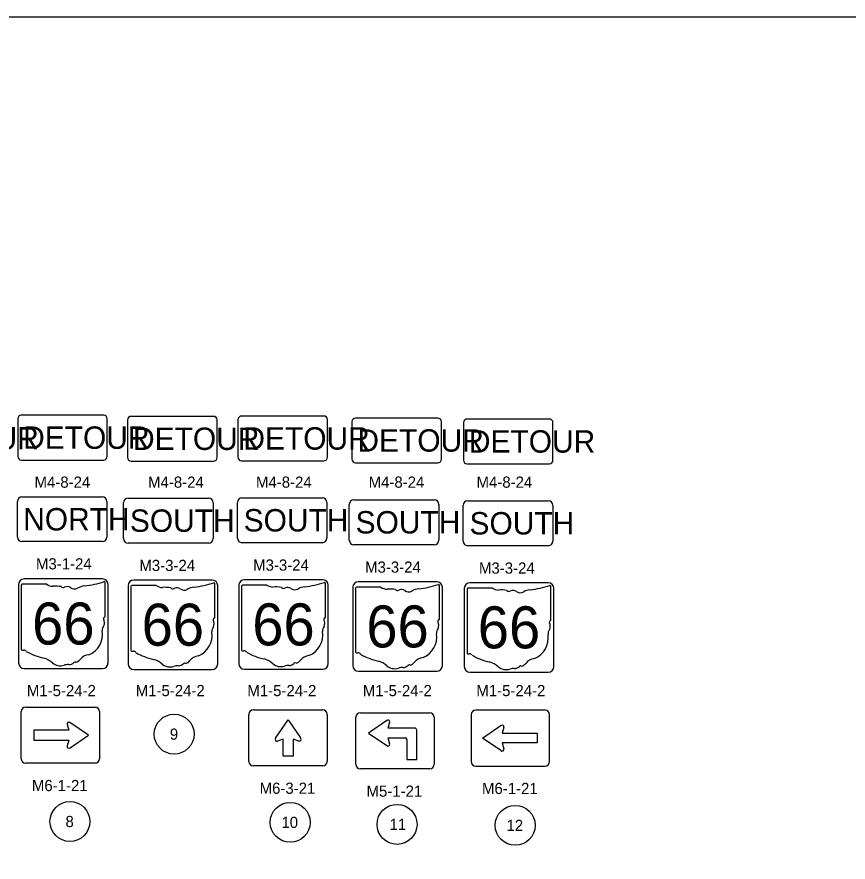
# Model space of a CAD drawing. Extents: x -87 to 2145, y -2128 to 440.
# Drawn here: x 565.1 to 750.8, y -339.7 to -150.9 of the extents above; entities that cross this region are included whole.
import ezdxf

# ---------------------------------------------------------------- set-up
doc = ezdxf.new("R2010")
doc.units = 0
for name, color, linetype in [('Default', 7, 'Continuous'), ('SC_Scratch1', 7, 'Continuous'), ('SN_P_Signs', 7, 'Continuous'), ('SN_P_Text', 7, 'Continuous')]:
    doc.layers.add(name, color=color, linetype=linetype)

msp = doc.modelspace()

# ---------------------------------------------------------------- linework, layer by layer
at = {"layer": 'Default'}
for centre in [(600.26, -311.12), (576.98, -330.63), (626.19, -330.82), (650.06, -331.27), (676.46, -331.49)]:
    msp.add_circle(centre, 4.46, dxfattribs=at)
at = {"layer": 'SC_Scratch1'}
msp.add_lwpolyline([(-86.99, -150.94), (902.07, -150.94), (902.07, -726.16), (-86.99, -726.16)], close=True, dxfattribs=at)
at = {"layer": 'SN_P_Signs'}
for p, q in [((566.24, -258.13), (584.24, -258.13)), ((589.98, -258.44), (607.98, -258.44)), ((615.39, -258.36), (633.39, -258.36)), ((565.24, -267.13), (565.24, -259.13)), ((585.24, -259.13), (585.24, -267.13)), ((588.98, -267.44), (588.98, -259.44)), ((608.98, -259.44), (608.98, -267.44)), ((614.39, -267.36), (614.39, -259.36)), ((634.39, -259.36), (634.39, -267.36)), ((639.4, -267.81), (639.4, -259.81)), ((640.4, -258.81), (658.4, -258.81)), ((659.4, -259.81), (659.4, -267.81)), ((664.85, -268.03), (664.85, -260.03)), ((665.85, -259.03), (683.85, -259.03)), ((684.85, -260.03), (684.85, -268.03)), ((584.24, -268.13), (566.24, -268.13)), ((607.98, -268.44), (589.98, -268.44)), ((633.39, -268.36), (615.39, -268.36)), ((658.4, -268.81), (640.4, -268.81)), ((683.85, -269.03), (665.85, -269.03)), ((584.87, -284.73), (584.87, -277.29)), ((634.07, -284.92), (634.07, -277.47)), ((566.12, -277.89), (566.12, -292.12)), ((571.8, -277.64), (566.31, -277.64)), ((590.6, -278.15), (590.6, -292.38)), ((596.28, -277.9), (590.79, -277.9)), ((609.35, -284.99), (609.35, -277.55)), ((615.32, -278.07), (615.32, -292.3)), ((620.99, -277.82), (615.5, -277.82)), ((640.79, -278.52), (640.79, -292.75)), ((646.47, -278.28), (640.98, -278.28)), ((659.54, -285.37), (659.54, -277.93)), ((665.69, -278.74), (665.69, -292.97)), ((671.37, -278.49), (665.88, -278.49)), ((684.44, -285.58), (684.44, -278.14)), ((584.87, -284.73), (584.87, -284.73)), ((609.35, -284.99), (609.35, -284.99)), ((634.07, -284.91), (634.07, -284.92)), ((659.54, -285.37), (659.54, -285.37)), ((684.44, -285.58), (684.44, -285.58)), ((567.11, -305.1), (582.61, -305.1)), ((617.97, -305.7), (633.47, -305.7)), ((683.15, -305.75), (667.65, -305.75)), ((683.15, -305.75), (683.15, -305.75)), ((566.11, -316.6), (566.11, -306.1)), ((583.61, -306.1), (583.61, -316.6)), ((616.97, -317.2), (616.97, -306.7)), ((634.47, -306.7), (634.47, -317.2)), ((640.86, -317.85), (640.86, -307.35)), ((641.86, -306.35), (657.36, -306.35)), ((658.36, -307.35), (658.36, -317.85)), ((666.65, -306.75), (666.65, -317.25)), ((684.15, -317.25), (684.15, -306.75)), ((576.34, -308.98), (576.73, -310.26)), ((581.11, -311.35), (576.97, -308.51)), ((622.88, -312.02), (625.72, -307.89)), ((625.72, -307.89), (628.52, -311.97)), ((647.75, -308.08), (643.67, -310.88)), ((648.05, -309.78), (648.46, -308.38)), ((669.15, -312), (673.29, -309.15)), ((576.73, -310.26), (568.92, -310.26)), ((568.92, -310.26), (568.92, -312.45)), ((577.03, -314.15), (581.11, -311.35)), ((643.67, -310.88), (647.75, -313.67)), ((653.98, -309.78), (648.05, -309.78)), ((653.98, -309.78), (653.98, -309.78)), ((654.45, -316.82), (654.45, -310.25)), ((673.93, -309.62), (673.53, -310.9)), ((673.53, -310.9), (681.34, -310.9)), ((681.34, -310.9), (681.34, -313.09)), ((568.92, -312.45), (576.73, -312.45)), ((576.73, -312.45), (576.34, -313.73)), ((624.63, -312.26), (623.35, -312.66)), ((624.63, -316.01), (624.63, -312.26)), ((628.1, -312.66), (626.82, -312.26)), ((626.82, -312.26), (626.82, -316.01)), ((648.46, -313.38), (648.05, -311.97)), ((648.05, -311.97), (651.95, -311.97)), ((652.26, -312.28), (652.26, -316.82)), ((673.23, -314.79), (669.15, -312)), ((681.34, -313.09), (673.53, -313.09)), ((673.53, -313.09), (673.93, -314.37)), ((626.82, -316.01), (624.63, -316.01)), ((652.26, -316.82), (654.45, -316.82)), ((652.26, -316.82), (654.45, -316.82)), ((582.61, -317.6), (567.11, -317.6)), ((633.47, -318.2), (617.97, -318.2)), ((657.36, -318.85), (641.86, -318.85)), ((667.65, -318.25), (683.15, -318.25))]:
    msp.add_line(p, q, dxfattribs=at)
for points in [[(565.32, -240.7), (565.32, -249.1)], [(584.52, -239.9), (566.12, -239.9)], [(585.32, -249.1), (585.32, -240.7)], [(589.86, -240.95), (589.86, -249.35)], [(609.06, -240.15), (590.66, -240.15)], [(609.86, -249.35), (609.86, -240.95)], [(614.52, -240.88), (614.52, -249.28)], [(633.72, -240.08), (615.32, -240.08)], [(634.52, -249.28), (634.52, -240.88)], [(639.99, -241.33), (639.99, -249.73)], [(659.19, -240.53), (640.79, -240.53)], [(659.99, -249.73), (659.99, -241.33)], [(664.89, -241.55), (664.89, -249.95)], [(684.09, -240.75), (665.69, -240.75)], [(684.89, -249.95), (684.89, -241.55)], [(566.12, -249.9), (584.52, -249.9)], [(590.66, -250.15), (609.06, -250.15)], [(615.32, -250.08), (633.72, -250.08)], [(640.79, -250.53), (659.19, -250.53)], [(665.69, -250.75), (684.09, -250.75)], [(584.26, -276.45), (566.76, -276.45)], [(608.74, -276.7), (591.24, -276.7)], [(633.46, -276.63), (615.96, -276.63)], [(658.93, -277.08), (641.43, -277.08)], [(683.83, -277.3), (666.33, -277.3)], [(565.51, -277.7), (565.51, -295.2)], [(585.51, -295.2), (585.51, -277.7)], [(589.99, -277.95), (589.99, -295.45)], [(609.99, -295.45), (609.99, -277.95)], [(614.71, -277.88), (614.71, -295.38)], [(634.71, -295.38), (634.71, -277.88)], [(640.18, -278.33), (640.18, -295.83)], [(660.18, -295.83), (660.18, -278.33)], [(665.08, -278.55), (665.08, -296.05)], [(685.08, -296.05), (685.08, -278.55)], [(566.76, -296.45), (584.26, -296.45)], [(591.24, -296.7), (608.74, -296.7)], [(615.96, -296.63), (633.46, -296.63)], [(641.43, -297.08), (658.93, -297.08)], [(666.33, -297.3), (683.83, -297.3)]]:
    msp.add_lwpolyline(points, dxfattribs=at)
for centre, radius, start, end in [((566.12, -240.7), 0.8, 90, 180), ((584.52, -240.7), 0.8, 0, 90), ((590.66, -240.95), 0.8, 90, 180), ((609.06, -240.95), 0.8, 0, 90), ((615.32, -240.88), 0.8, 90, 180), ((633.72, -240.88), 0.8, 0, 90), ((640.79, -241.33), 0.8, 90, 180), ((659.19, -241.33), 0.8, 0, 90), ((665.69, -241.55), 0.8, 90, 180), ((684.09, -241.55), 0.8, 0, 90), ((566.12, -249.1), 0.8, 180, 270), ((584.52, -249.1), 0.8, 270, 0), ((590.66, -249.35), 0.8, 180, 270), ((609.06, -249.35), 0.8, 270, 0), ((615.32, -249.28), 0.8, 180, 270), ((633.72, -249.28), 0.8, 270, 0), ((640.79, -249.73), 0.8, 180, 270), ((659.19, -249.73), 0.8, 270, 0), ((665.69, -249.95), 0.8, 180, 270), ((684.09, -249.95), 0.8, 270, 0), ((566.24, -259.13), 1, 90, 180), ((584.24, -259.13), 1, 0, 90), ((589.98, -259.44), 1, 90, 180), ((607.98, -259.44), 1, 0, 90), ((615.39, -259.36), 1, 90, 180), ((633.39, -259.36), 1, 0, 90), ((640.4, -259.81), 1, 90, 180), ((658.4, -259.81), 1, 0, 90), ((665.85, -260.03), 1, 90, 180), ((683.85, -260.03), 1, 0, 90), ((566.24, -267.13), 1, 180, 270), ((584.24, -267.13), 1, 270, 0), ((589.98, -267.44), 1, 180, 270), ((607.98, -267.44), 1, 270, 0), ((615.39, -267.36), 1, 180, 270), ((633.39, -267.36), 1, 270, 0), ((640.4, -267.81), 1, 180, 270), ((658.4, -267.81), 1, 270, 0), ((665.85, -268.03), 1, 180, 270), ((683.85, -268.03), 1, 270, 0), ((566.76, -277.7), 1.25, 90, 180), ((578.19, -258.24), 19.88, 275.8445, 288.9065), ((584.26, -277.7), 1.25, 0, 90), ((584.66, -277.26), 0.209, 351.8621, 97.738), ((591.24, -277.95), 1.25, 90, 180), ((602.67, -258.5), 19.88, 275.8445, 288.9065), ((608.74, -277.95), 1.25, 0, 90), ((609.15, -277.52), 0.209, 351.8621, 97.738), ((615.96, -277.88), 1.25, 90, 180), ((627.39, -258.42), 19.88, 275.8445, 288.9065), ((633.46, -277.88), 1.25, 0, 90), ((633.86, -277.44), 0.209, 351.8621, 97.738), ((641.43, -278.33), 1.25, 90, 180), ((658.93, -278.33), 1.25, 0, 90), ((666.33, -278.55), 1.25, 90, 180), ((683.83, -278.55), 1.25, 0, 90), ((566.34, -277.86), 0.217, 98.1301, 188.1301), ((573.1, -275.99), 2.11, 231.6195, 271.1119), ((573.8, -285.63), 7.56, 80.4867, 94.9883), ((575.52, -277.78), 0.608, 219.7921, 297.1024), ((576.41, -279.43), 1.26, 54.4667, 119.1411), ((578.04, -277.17), 1.52, 233.8562, 294.8282), ((580.73, -281.99), 4, 97.3462, 120.7689), ((590.82, -278.12), 0.217, 98.1301, 188.1301), ((597.59, -276.25), 2.11, 231.6195, 271.1119), ((598.29, -285.89), 7.56, 80.4867, 94.9883), ((600, -278.04), 0.608, 219.7921, 297.1024), ((600.9, -279.69), 1.26, 54.4667, 119.1411), ((602.53, -277.43), 1.52, 233.8562, 294.8282), ((605.21, -282.25), 4, 97.3462, 120.7689), ((615.53, -278.04), 0.217, 98.1301, 188.1301), ((622.3, -276.17), 2.11, 231.6195, 271.1119), ((623, -285.81), 7.56, 80.4867, 94.9883), ((624.72, -277.96), 0.608, 219.7921, 297.1024), ((625.61, -279.61), 1.26, 54.4667, 119.1411), ((627.24, -277.35), 1.52, 233.8562, 294.8282), ((629.93, -282.17), 4, 97.3462, 120.7689), ((641.01, -278.49), 0.217, 98.1301, 188.1301), ((647.78, -276.63), 2.11, 231.6195, 271.1119), ((648.48, -286.27), 7.56, 80.4867, 94.9883), ((650.19, -278.42), 0.608, 219.7921, 297.1024), ((651.09, -280.06), 1.26, 54.4667, 119.1411), ((652.72, -277.81), 1.52, 233.8562, 294.8282), ((655.4, -282.62), 4, 97.3462, 120.7689), ((652.86, -258.88), 19.88, 275.8445, 288.9065), ((659.34, -277.89), 0.209, 351.8621, 97.738), ((665.91, -278.71), 0.217, 98.1301, 188.1301), ((672.68, -276.84), 2.11, 231.6195, 271.1119), ((673.37, -286.48), 7.56, 80.4867, 94.9883), ((675.09, -278.63), 0.608, 219.7921, 297.1024), ((675.98, -280.28), 1.26, 54.4667, 119.1411), ((677.61, -278.02), 1.52, 233.8562, 294.8282), ((680.3, -282.84), 4, 97.3462, 120.7689), ((677.76, -259.09), 19.88, 275.8445, 288.9065), ((684.23, -278.11), 0.209, 351.8621, 97.738), ((584.82, -285.28), 0.323, 107.944, 210.337), ((584.65, -284.76), 0.223, 289.6038, 7.7341), ((609.13, -285.02), 0.223, 289.6038, 7.7341), ((633.85, -284.94), 0.223, 289.6038, 7.7341), ((585.62, -287.85), 1.41, 136.8065, 186.9296), ((582.77, -286.22), 1.94, 340.033, 23.6496), ((609.31, -285.54), 0.323, 107.944, 210.337), ((607.25, -286.48), 1.94, 340.033, 23.6496), ((634.02, -285.46), 0.323, 107.944, 210.337), ((631.97, -286.4), 1.94, 340.033, 23.6496), ((659.5, -285.92), 0.323, 107.944, 210.337), ((657.44, -286.86), 1.94, 340.033, 23.6496), ((659.32, -285.4), 0.223, 289.6038, 7.7341), ((684.39, -286.13), 0.323, 107.944, 210.337), ((682.34, -287.07), 1.94, 340.033, 23.6496), ((684.22, -285.61), 0.223, 289.6038, 7.7341), ((579.31, -288.8), 4.97, 292.3089, 8.9858), ((603.79, -289.06), 4.97, 292.3089, 8.9858), ((610.1, -288.11), 1.41, 136.8065, 186.9296), ((628.5, -288.98), 4.97, 292.3089, 8.9858), ((634.82, -288.03), 1.41, 136.8065, 186.9296), ((653.98, -289.43), 4.97, 292.3089, 8.9858), ((660.29, -288.48), 1.41, 136.8065, 186.9296), ((685.19, -288.7), 1.41, 136.8065, 186.9296), ((678.88, -289.65), 4.97, 292.3089, 8.9858), ((566.34, -292.15), 0.219, 171.9584, 258.3066), ((566.37, -290.69), 1.67, 267.339, 280.6039), ((566.71, -292.94), 0.603, 29.7484, 93.2717), ((590.82, -292.41), 0.219, 171.9584, 258.3066), ((615.54, -292.33), 0.219, 171.9584, 258.3066), ((615.57, -290.87), 1.67, 267.339, 280.6039), ((615.91, -293.12), 0.603, 29.7484, 93.2717), ((574.33, -280.15), 14.36, 240.4129, 257.1985), ((570.05, -298.51), 4.49, 47.1842, 75.836), ((577.95, -293.5), 1.61, 282.8732, 323.2771), ((581.4, -296.11), 2.72, 94.4031, 142.5768), ((590.85, -290.95), 1.67, 267.339, 280.6039), ((591.2, -293.2), 0.603, 29.7484, 93.2717), ((598.81, -280.41), 14.36, 240.4129, 257.1985), ((594.53, -298.77), 4.49, 47.1842, 75.836), ((605.89, -296.37), 2.72, 94.4031, 142.5768), ((623.52, -280.33), 14.36, 240.4129, 257.1985), ((619.24, -298.69), 4.49, 47.1842, 75.836), ((630.6, -296.29), 2.72, 94.4031, 142.5768), ((641.01, -292.78), 0.219, 171.9584, 258.3066), ((641.04, -291.33), 1.67, 267.339, 280.6039), ((641.39, -293.57), 0.603, 29.7484, 93.2717), ((649, -280.79), 14.36, 240.4129, 257.1985), ((656.08, -296.75), 2.72, 94.4031, 142.5768), ((665.91, -293), 0.219, 171.9584, 258.3066), ((665.94, -291.54), 1.67, 267.339, 280.6039), ((666.28, -293.79), 0.603, 29.7484, 93.2717), ((673.9, -281), 14.36, 240.4129, 257.1985), ((680.97, -296.96), 2.72, 94.4031, 142.5768), ((566.76, -295.2), 1.25, 180, 270), ((574.9, -293.01), 2.85, 230.7004, 286.2918), ((576.55, -297.93), 2.34, 85.6951, 111.2099), ((576.76, -294.08), 1.52, 268.777, 315.5493), ((578.13, -295.45), 0.428, 65.7517, 132.6484), ((584.26, -295.2), 1.25, 270, 0), ((591.24, -295.45), 1.25, 180, 270), ((599.39, -293.27), 2.85, 230.7004, 286.2918), ((601.03, -298.19), 2.34, 85.6951, 111.2099), ((601.24, -294.33), 1.52, 268.777, 315.5493), ((602.62, -295.71), 0.428, 65.7517, 132.6484), ((602.43, -293.76), 1.61, 282.8732, 323.2771), ((608.74, -295.45), 1.25, 270, 0), ((615.96, -295.38), 1.25, 180, 270), ((624.1, -293.19), 2.85, 230.7004, 286.2918), ((625.75, -298.11), 2.34, 85.6951, 111.2099), ((625.96, -294.26), 1.52, 268.777, 315.5493), ((627.33, -295.64), 0.428, 65.7517, 132.6484), ((627.15, -293.68), 1.61, 282.8732, 323.2771), ((633.46, -295.38), 1.25, 270, 0), ((641.43, -295.83), 1.25, 180, 270), ((644.72, -299.15), 4.49, 47.1842, 75.836), ((649.58, -293.65), 2.85, 230.7004, 286.2918), ((651.22, -298.57), 2.34, 85.6951, 111.2099), ((651.43, -294.71), 1.52, 268.777, 315.5493), ((652.81, -296.09), 0.428, 65.7517, 132.6484), ((652.62, -294.13), 1.61, 282.8732, 323.2771), ((658.93, -295.83), 1.25, 270, 0), ((666.33, -296.05), 1.25, 180, 270), ((669.62, -299.36), 4.49, 47.1842, 75.836), ((674.48, -293.86), 2.85, 230.7004, 286.2918), ((676.33, -294.93), 1.52, 268.777, 315.5493), ((677.7, -296.3), 0.428, 65.7517, 132.6484), ((677.52, -294.35), 1.61, 282.8732, 323.2771), ((683.83, -296.05), 1.25, 270, 0), ((676.12, -298.78), 2.34, 85.6951, 111.2099), ((567.11, -306.1), 1, 90, 180), ((582.61, -306.1), 1, 0, 90), ((617.97, -306.7), 1, 90, 180), ((633.47, -306.7), 1, 0, 90), ((667.65, -306.75), 1, 90, 180), ((683.15, -306.75), 1, 0, 90), ((641.86, -307.35), 1, 90, 180), ((657.36, -307.35), 1, 0, 90), ((576.73, -308.85), 0.417, 55.4112, 197.2046), ((648.05, -308.38), 0.417, 0.0017, 134.9999), ((673.53, -309.5), 0.417, 342.7954, 124.5888), ((653.98, -310.25), 0.469, 0, 90), ((623.22, -312.26), 0.417, 145.4112, 287.2046), ((628.22, -312.26), 0.417, 252.7954, 45.0096), ((651.95, -312.28), 0.312, 0, 90), ((576.73, -313.85), 0.417, 162.7954, 315.0096), ((648.05, -313.38), 0.417, 225.0001, 0.0017), ((673.53, -314.5), 0.417, 224.9904, 17.2046), ((567.11, -316.6), 1, 180, 270), ((582.61, -316.6), 1, 270, 360), ((617.97, -317.2), 1, 180, 270), ((633.47, -317.2), 1, 270, 0), ((641.86, -317.85), 1, 180, 270), ((657.36, -317.85), 1, 270, 360), ((667.65, -317.25), 1, 180, 270), ((683.15, -317.25), 1, 270, 0)]:
    msp.add_arc(centre, radius, start, end, dxfattribs=at)

# ---------------------------------------------------------------- texts
at = {"layer": 'Default'}
for s, p in [('9', (599.3, -312.37)), ('8', (575.99, -331.88)), ('10', (624.23, -332.07)), ('11', (648.38, -332.52)), ('12', (674.51, -332.74))]:
    msp.add_text(s, height=2.5, dxfattribs=at).set_placement(p)
at = {"layer": 'SN_P_Signs'}
for s, height, p in [('DETOUR', 5, (541.8, -247.55)), ('DETOUR', 5, (566.53, -247.4)), ('DETOUR', 5, (591.08, -247.65)), ('DETOUR', 5, (615.73, -247.58)), ('DETOUR', 5, (641.21, -248.03)), ('DETOUR', 5, (666.11, -248.25)), ('NORTH', 5, (566.54, -265.63)), ('SOUTH', 5, (590.38, -265.94)), ('SOUTH', 5, (615.79, -265.86)), ('SOUTH', 5, (640.8, -266.31)), ('SOUTH', 5, (666.25, -266.53)), ('66', 9.375, (568.53, -291.11)), ('66', 9.375, (593.01, -291.37)), ('66', 9.375, (617.72, -291.3)), ('66', 9.375, (643.2, -291.75)), ('66', 9.375, (668.1, -291.96))]:
    msp.add_text(s, height=height, dxfattribs=at).set_placement(p)
at = {"layer": 'SN_P_Text'}
for s, p in [('M4-8-24', (569.08, -256.09)), ('M4-8-24', (594.44, -256.09)), ('M4-8-24', (618.55, -256.09)), ('M4-8-24', (643.71, -256.09)), ('M4-8-24', (667.82, -256.09)), ('M3-1-24', (569.4, -274.33)), ('M3-3-24', (592.5, -274.69)), ('M3-3-24', (617.91, -274.61)), ('M3-3-24', (642.92, -275.06)), ('M3-3-24', (668.37, -275.28)), ('M1-5-24-2', (567.36, -302.64)), ('M1-5-24-2', (591.68, -302.64)), ('M1-5-24-2', (616.62, -302.64)), ('M1-5-24-2', (642.41, -302.64)), ('M1-5-24-2', (667.78, -302.64)), ('M6-1-21', (568.49, -323.85)), ('M6-3-21', (619.36, -324.45)), ('M5-1-21', (643.24, -325.1)), ('M6-1-21', (669.04, -324.5))]:
    msp.add_text(s, height=2.5, dxfattribs=at).set_placement(p)

doc.saveas('drawing.dxf')
